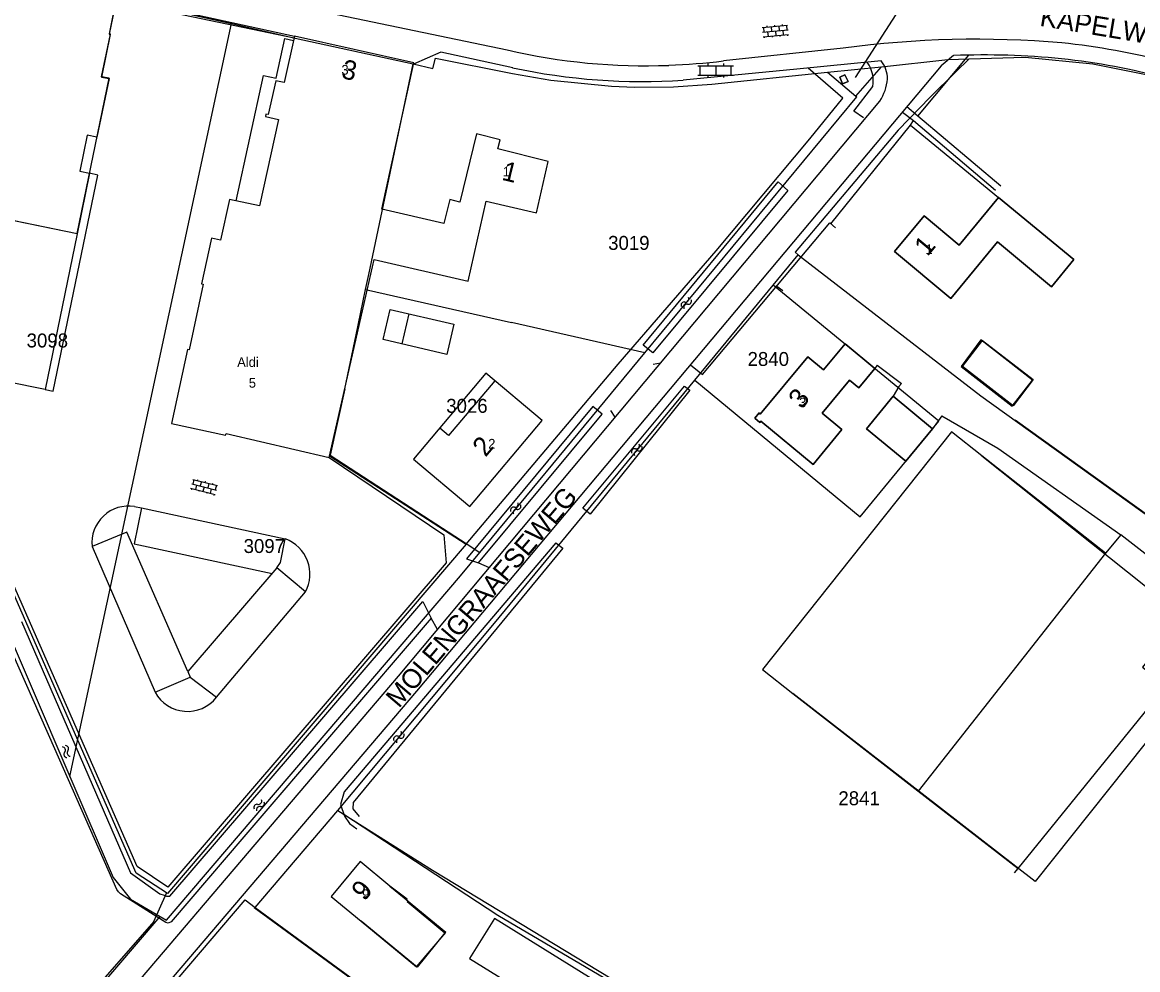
# Model space of a CAD drawing. Extents: x 148816 to 151297, y 399515 to 402500.
# Drawn here: x 149556.2 to 149700.3, y 399853.8 to 399976.1 of the extents above; entities that cross this region are included whole.
import ezdxf

# ---------------------------------------------------------------- set-up
doc = ezdxf.new("R2010")
doc.units = 0
for name, color, linetype in [('B01 Hoofdgebouw  [D] Norm', 7, 'Continuous'), ('B01 Hoofdgebouw  [T] Norm', 7, 'Continuous'), ('B01 hoofgebouw', 7, 'Continuous'), ('B02 Bijgebouw  [D] Norm', 7, 'Continuous'), ('B02 Bijgebouw  [T] Norm', 7, 'Continuous'), ('B03 Overig opstal  [D] Norm', 7, 'Continuous'), ('G01 perceelsgrens', 7, 'Continuous'), ('Q01 Spoorrail  [D] Norm', 7, 'Continuous'), ('S02 Open verharding  Norm', 7, 'Continuous'), ('S05 Water  Norm', 7, 'Continuous'), ('T04 Haag heg  [D] Gem', 7, 'Continuous'), ('T09 Insteek water  [T] Norm', 7, 'Continuous'), ('V00 Kant verharding algemeen  [T] Norm', 7, 'Continuous'), ('V00 Kant verharding algemeen secundair  [T] Gem', 7, 'Continuous'), ('Z01 perceelnummer', 7, 'Continuous'), ('Z02 huisnummer', 7, 'Continuous'), ('Z02 Huisnummer  [Tekst] Norm', 7, 'Continuous'), ('Z06 straatnaam', 7, 'Continuous'), ('Z19 Overige Tekst  [Tekst] Gem', 7, 'Continuous')]:
    doc.layers.add(name, color=color, linetype=linetype)

msp = doc.modelspace()

# ---------------------------------------------------------------- linework, layer by layer
at = {"layer": 'B01 Hoofdgebouw  [D] Norm'}
for p, q in [((149696.14, 399907.52), (149680.2, 399920.1)), ((149698.12, 399909.89), (149696.14, 399907.52)), ((149711.47, 399899.6), (149698.12, 399909.89)), ((149696.14, 399907.52), (149671.95, 399876.8)), ((149684.88, 399866.84), (149711.47, 399899.6)), ((149655.75, 399889.41), (149671.91, 399876.83)), ((149671.91, 399876.83), (149684.88, 399866.84)), ((149605.93, 399862.88), (149603.68, 399864.52)), ((149605.82, 399862.71), (149605.93, 399862.88)), ((149610.91, 399858.57), (149605.82, 399862.71)), ((149599.97, 399860.03), (149607.15, 399854.11)), ((149617.21, 399860.35), (149613.99, 399855.18)), ((149645.48, 399842.9), (149617.21, 399860.35)), ((149607.15, 399854.11), (149610.91, 399858.57)), ((149613.99, 399855.18), (149642.3, 399837.81)), ((149613.99, 399855.18), (149613.99, 399855.18))]:
    msp.add_line(p, q, dxfattribs=at)
at = {"layer": 'B01 Hoofdgebouw  [T] Norm'}
for p, q in [((149662.46, 399969.29), (149661.82, 399968.98)), ((149661.82, 399968.98), (149662.18, 399968.14)), ((149662.9, 399968.43), (149662.46, 399969.29)), ((149662.18, 399968.14), (149662.9, 399968.43)), ((149682.32, 399953.48), (149677.26, 399947.3)), ((149692.06, 399945.46), (149682.32, 399953.48)), ((149672.71, 399951.08), (149668.89, 399946.49)), ((149677.26, 399947.3), (149672.71, 399951.08)), ((149676.16, 399940.44), (149682.22, 399947.72)), ((149682.22, 399947.72), (149689.19, 399941.91)), ((149668.89, 399946.49), (149676.16, 399940.44)), ((149689.19, 399941.91), (149692.06, 399945.46)), ((149662.5, 399934.55), (149659.72, 399931.21)), ((149666.34, 399931.37), (149662.5, 399934.55)), ((149657.69, 399932.89), (149651.55, 399925.5)), ((149659.72, 399931.21), (149657.69, 399932.89)), ((149664.28, 399928.88), (149666.34, 399931.37)), ((149659.57, 399925.62), (149663.09, 399929.87)), ((149663.09, 399929.87), (149664.28, 399928.88)), ((149665.28, 399923.61), (149668.74, 399927.79)), ((149668.74, 399927.79), (149673.81, 399923.58)), ((149651.4, 399925.65), (149650.83, 399924.98)), ((149651.55, 399925.5), (149651.4, 399925.65)), ((149662.11, 399923.51), (149659.57, 399925.62)), ((149650.83, 399924.98), (149651.5, 399924.42)), ((149651.5, 399924.42), (149651.64, 399924.59)), ((149651.64, 399924.59), (149658.38, 399919)), ((149676.28, 399923.22), (149651.83, 399892.53)), ((149658.38, 399919), (149662.11, 399923.51)), ((149670.35, 399919.4), (149665.28, 399923.61)), ((149673.81, 399923.58), (149670.35, 399919.4)), ((149680.2, 399920.1), (149676.28, 399923.22)), ((149651.83, 399892.53), (149655.75, 399889.41)), ((149599.83, 399867.71), (149596.11, 399863.22)), ((149603.68, 399864.52), (149599.83, 399867.71)), ((149596.11, 399863.22), (149599.97, 399860.03))]:
    msp.add_line(p, q, dxfattribs=at)
for points in [[(149539.35, 399953.68), (149545.61, 399983.79), (149565.21, 399979.72), (149565.17, 399979.54), (149568.32, 399978.9), (149567.41, 399974.55), (149567.55, 399974.52), (149566.42, 399969.01), (149567.4, 399968.81), (149565.84, 399961.24), (149564.58, 399961.5), (149563.62, 399956.85), (149564.89, 399956.59), (149563.27, 399948.75), (149539.35, 399953.68)], [(149563.27, 399948.75), (149559.13, 399928.66), (149554.23, 399929.67)]]:
    msp.add_lwpolyline(points, dxfattribs=at)
for points in [[(149606.8, 399970.86), (149591.36, 399974.28), (149590.04, 399968.3), (149588.97, 399968.54), (149587.96, 399964.17), (149587.67, 399964.23), (149587.6, 399963.92), (149589.3, 399963.53), (149586.86, 399952.37), (149582.96, 399953.22), (149581.81, 399947.96), (149580.63, 399948.23), (149579.36, 399942.3), (149579.58, 399942.26), (149577.77, 399933.79), (149577.54, 399933.84), (149575.48, 399924.28), (149582.47, 399922.76), (149582.52, 399922.98), (149595.83, 399919.88), (149601.66, 399945.44), (149613.79, 399942.67), (149616.14, 399952.98), (149622.64, 399951.5), (149624.15, 399958.12), (149617.65, 399959.73), (149617.94, 399960.92), (149614.9, 399961.67), (149612.74, 399952.86), (149611.43, 399953.19), (149610.67, 399950.12), (149602.64, 399951.96)], [(149614.01, 399913.55), (149623.37, 399924.66), (149616.09, 399930.76), (149606.75, 399919.67)]]:
    msp.add_lwpolyline(points, close=True, dxfattribs=at)
at = {"layer": 'B01 hoofgebouw'}
for points in [[(149539.4, 399953.71), (149563.3, 399948.8), (149567.42, 399968.85), (149566.44, 399969.05), (149567.57, 399974.56), (149567.45, 399974.58), (149568.34, 399978.92), (149565.19, 399979.57), (149565.23, 399979.74), (149545.63, 399983.78)], [(149624.15, 399958.12), (149617.65, 399959.73), (149617.94, 399960.92), (149614.9, 399961.67), (149612.74, 399952.86), (149611.43, 399953.19), (149610.67, 399950.12), (149602.64, 399951.96), (149606.75, 399970.66), (149606.8, 399970.86), (149591.36, 399974.28), (149590.04, 399968.3), (149588.97, 399968.54), (149587.96, 399964.17), (149587.67, 399964.23), (149587.6, 399963.92), (149589.3, 399963.53), (149586.86, 399952.37), (149582.96, 399953.22), (149581.81, 399947.96), (149580.63, 399948.23), (149579.36, 399942.3), (149579.58, 399942.26), (149577.77, 399933.79), (149577.54, 399933.84), (149575.48, 399924.28), (149582.47, 399922.76), (149582.52, 399922.98), (149595.83, 399919.88)], [(149662.18, 399968.14), (149661.82, 399968.98), (149662.46, 399969.29), (149662.9, 399968.43), (149662.18, 399968.14)], [(149595.83, 399919.88), (149601.66, 399945.44), (149613.79, 399942.67), (149616.14, 399952.98), (149622.64, 399951.5), (149624.15, 399958.12)], [(149672.71, 399951.08), (149677.26, 399947.3), (149682.32, 399953.48), (149692.06, 399945.46), (149689.19, 399941.91), (149682.22, 399947.72), (149676.16, 399940.44), (149668.89, 399946.49), (149672.71, 399951.08)], [(149611.07, 399933.2), (149602.82, 399935.12), (149603.72, 399939.01), (149611.97, 399937.1), (149611.07, 399933.2)], [(149650.83, 399924.98), (149651.4, 399925.65), (149651.55, 399925.5), (149657.69, 399932.89), (149659.72, 399931.21), (149662.5, 399934.55), (149666.34, 399931.37), (149664.28, 399928.88), (149663.09, 399929.87), (149659.57, 399925.62), (149662.11, 399923.51), (149658.38, 399919), (149651.64, 399924.59), (149651.5, 399924.42), (149650.83, 399924.98)], [(149686.82, 399929.95), (149684.21, 399926.57), (149677.67, 399931.64), (149680.27, 399935), (149686.82, 399929.95)], [(149614.01, 399913.55), (149623.37, 399924.66), (149616.09, 399930.76), (149606.75, 399919.67), (149614.01, 399913.55)], [(149668.74, 399927.79), (149665.28, 399923.61), (149670.35, 399919.4), (149673.81, 399923.58), (149668.74, 399927.79)], [(149680.2, 399920.1), (149676.28, 399923.22), (149651.83, 399892.53), (149655.75, 399889.41)], [(149680.2, 399920.1), (149706.18, 399899.4), (149700.94, 399892.82), (149706.02, 399888.9), (149687.08, 399865.13), (149655.75, 399889.41)], [(149603.68, 399864.52), (149599.83, 399867.71), (149596.11, 399863.22), (149599.97, 399860.03)], [(149603.68, 399864.52), (149606.01, 399862.64), (149605.94, 399862.56), (149610.81, 399858.51)], [(149610.81, 399858.51), (149607.2, 399854.07), (149599.97, 399860.03)]]:
    msp.add_lwpolyline(points, dxfattribs=at)
at = {"layer": 'B02 Bijgebouw  [D] Norm'}
for p, q in [((149680.06, 399935.1), (149677.52, 399931.66)), ((149686.72, 399929.89), (149680.06, 399935.1)), ((149677.52, 399931.66), (149684.11, 399926.51)), ((149684.11, 399926.51), (149686.72, 399929.89)), ((149686.72, 399929.89), (149686.72, 399929.89))]:
    msp.add_line(p, q, dxfattribs=at)
at = {"layer": 'B02 Bijgebouw  [T] Norm'}
msp.add_lwpolyline([(149611.07, 399933.2), (149602.82, 399935.12), (149603.72, 399939.01), (149611.97, 399937.1)], close=True, dxfattribs=at)
at = {"layer": 'B03 Overig opstal  [D] Norm'}
msp.add_line((149606.16, 399938.45), (149605.23, 399934.56), dxfattribs=at)
msp.add_lwpolyline([(149617.24, 399929.8), (149611.28, 399922.72), (149610.13, 399923.69)], dxfattribs=at)
at = {"layer": 'G01 perceelsgrens'}
for points in [[(149567.23, 399979.52), (149583.22, 399975.91)], [(149562.35, 399878.68), (149583.22, 399975.91)], [(149583.22, 399975.91), (149591.46, 399974.05), (149606.68, 399970.71)], [(149606.68, 399970.71), (149609.22, 399970.14), (149609.58, 399971.44), (149619.55, 399969.47), (149624.49, 399968.61), (149632.33, 399967.82), (149635.3, 399967.71), (149640.32, 399967.77), (149645.31, 399968.11), (149660.24, 399969.66)], [(149678.53, 399971.35), (149685.79, 399971.6), (149694.54, 399970.72), (149703.15, 399968.98), (149712.62, 399965.67), (149738.18, 399954.78), (149747.36, 399950.83), (149750.02, 399949.48)], [(149600.55, 399941.59), (149600.95, 399943.53), (149606.68, 399970.71)], [(149678.53, 399971.35), (149676.84, 399969.68), (149673.51, 399966.42), (149669.39, 399962.16), (149656.05, 399946.39), (149656.45, 399946.07)], [(149660.24, 399969.66), (149667.23, 399970.35)], [(149663.89, 399966.54), (149667.23, 399970.35)], [(149667.23, 399970.35), (149675.78, 399971.26), (149678.53, 399971.35)], [(149660.24, 399969.66), (149663.89, 399966.54)], [(149636.65, 399933.4), (149664.01, 399966.44), (149663.89, 399966.54)], [(149653.21, 399942.14), (149656.45, 399946.07)], [(149656.45, 399946.07), (149680.04, 399927.84), (149734.15, 399889.05)], [(149599.33, 399935.71), (149600.55, 399941.59)], [(149600.55, 399941.59), (149619.4, 399937.32)], [(149643.11, 399929.88), (149664.46, 399912.24), (149674.64, 399924.6), (149653.21, 399942.14)], [(149643.11, 399929.88), (149653.21, 399942.14)], [(149636.65, 399933.4), (149619.4, 399937.32)], [(149597.88, 399928.76), (149599.33, 399935.71)], [(149632.33, 399928.18), (149636.65, 399933.4)], [(149596.96, 399874.3), (149617.22, 399898.48), (149643.11, 399929.88)], [(149597.88, 399928.76), (149595.97, 399920.18)], [(149615.31, 399907.63), (149632.33, 399928.18)], [(149595.97, 399920.18), (149608.04, 399912.34)], [(149547.19, 399913.98), (149562.35, 399878.68)], [(149608.04, 399912.34), (149613.67, 399908.69)], [(149613.67, 399908.69), (149615.31, 399907.63)], [(149612.82, 399904.62), (149615.31, 399907.63)], [(149574.02, 399860.62), (149574.81, 399860.15), (149612.82, 399904.62)], [(149562.35, 399878.68), (149567.95, 399865.64), (149570.18, 399862.88), (149574.02, 399860.62)], [(149586.3, 399861.77), (149596.96, 399874.3)], [(149596.96, 399874.3), (149609.21, 399866.6), (149652.26, 399840.54), (149650.89, 399833.39), (149685.52, 399809.42)], [(149552.31, 399731.81), (149538.32, 399785.32), (149537.24, 399793.27), (149538.02, 399800.67), (149540.43, 399807.68), (149544.81, 399814.17), (149544.03, 399814.85), (149584.99, 399862.77), (149586.3, 399861.77)], [(149530.37, 399795.59), (149531.12, 399802.31), (149534.21, 399810.97), (149539.3, 399818.63), (149538.57, 399819.27), (149574.02, 399860.62)], [(149586.3, 399861.77), (149675.13, 399796.74)]]:
    msp.add_lwpolyline(points, dxfattribs=at)
at = {"layer": 'Q01 Spoorrail  [D] Norm'}
for radius in [839.82, 838.32]:
    msp.add_arc((149374.9, 399222.57), radius, 47.97661, 67.90149, dxfattribs=at)
at = {"layer": 'S02 Open verharding  Norm'}
for p, q in [((149651.8, 399975.41), (149655.08, 399975.71)), ((149653.44, 399975.56), (149653.43, 399975.71)), ((149654.44, 399975.65), (149654.42, 399975.8)), ((149651.85, 399974.81), (149655.14, 399975.11)), ((149651.91, 399974.21), (149655.19, 399974.51)), ((149651.95, 399975.42), (149652, 399974.82)), ((149652.45, 399975.47), (149652.43, 399975.62)), ((149652.5, 399974.87), (149652.55, 399974.27)), ((149652.94, 399975.51), (149653, 399974.92)), ((149653.05, 399974.32), (149653.07, 399974.17)), ((149653.5, 399974.96), (149653.55, 399974.36)), ((149653.94, 399975.6), (149653.99, 399975.01)), ((149654.05, 399974.41), (149654.06, 399974.26)), ((149654.55, 399974.45), (149654.49, 399975.05)), ((149654.93, 399975.69), (149654.99, 399975.1)), ((149655.04, 399974.5), (149655.06, 399974.35)), ((149652.06, 399974.23), (149652.07, 399974.08)), ((149643.49, 399970.45), (149648.09, 399970.45)), ((149643.79, 399969.25), (149643.79, 399970.45)), ((149644.79, 399970.75), (149644.79, 399970.45)), ((149645.79, 399970.45), (149645.79, 399969.25)), ((149646.79, 399970.75), (149646.79, 399970.45)), ((149647.79, 399969.25), (149647.79, 399970.45)), ((149643.49, 399969.25), (149648.09, 399969.25)), ((149644.79, 399969.25), (149644.79, 399968.95)), ((149646.79, 399969.25), (149646.79, 399968.95)), ((149578.22, 399917.07), (149581.42, 399916.27)), ((149578.37, 399917.03), (149578.22, 399916.45)), ((149578.85, 399916.91), (149578.89, 399917.06)), ((149579.34, 399916.79), (149579.19, 399916.21)), ((149579.82, 399916.67), (149579.86, 399916.82)), ((149577.93, 399915.91), (149581.13, 399915.11)), ((149578.08, 399915.87), (149578.04, 399915.72)), ((149578.08, 399916.49), (149581.28, 399915.69)), ((149578.71, 399916.33), (149578.56, 399915.75)), ((149579.05, 399915.63), (149579.01, 399915.48)), ((149579.68, 399916.09), (149579.53, 399915.51)), ((149580.02, 399915.39), (149579.98, 399915.24)), ((149580.31, 399916.55), (149580.16, 399915.97)), ((149580.5, 399915.26), (149580.65, 399915.85)), ((149580.79, 399916.43), (149580.83, 399916.57)), ((149581.28, 399916.31), (149581.13, 399915.73)), ((149580.99, 399915.14), (149580.95, 399915))]:
    msp.add_line(p, q, dxfattribs=at)
at = {"layer": 'S05 Water  Norm'}
for centre, start, end in [((149641.73, 399939.55), 78.5608, 202.4158), ((149642.08, 399939.26), 78.5608, 202.4158), ((149641.9, 399940.38), 258.5608, 22.4158), ((149642.25, 399940.1), 258.5608, 22.4158), ((149635.34, 399920.6), 78.5608, 202.4158), ((149635.51, 399921.44), 258.5608, 22.4158), ((149635.85, 399921.15), 258.5608, 22.4158), ((149635.68, 399920.32), 78.5608, 202.4158), ((149619.86, 399913.89), 258.4991, 22.3541), ((149620.21, 399913.61), 258.4991, 22.3541), ((149619.69, 399913.06), 78.4991, 202.3541), ((149620.04, 399912.77), 78.4991, 202.3541), ((149604.6, 399883.51), 78.5608, 202.4158), ((149604.95, 399883.23), 78.5608, 202.4158), ((149604.77, 399884.35), 258.5608, 22.4158), ((149605.11, 399884.06), 258.5608, 22.4158), ((149561.34, 399882.11), 320.4187, 84.2737), ((149561.75, 399882.28), 320.4187, 84.2737), ((149561.99, 399881.56), 140.4187, 264.2737), ((149562.41, 399881.74), 140.4187, 264.2737), ((149586.53, 399874.69), 77.4834, 201.3384), ((149586.87, 399874.4), 77.4834, 201.3384), ((149586.71, 399875.52), 257.4833, 21.3384), ((149587.05, 399875.23), 257.4833, 21.3384)]:
    msp.add_arc(centre, 0.425, start, end, dxfattribs=at)
at = {"layer": 'T04 Haag heg  [D] Gem'}
for p, q in [((149671.89, 399963.98), (149678.5, 399971.85)), ((149662.23, 399966.29), (149657.75, 399970.18)), ((149657.94, 399961.02), (149662.23, 399966.29)), ((149660.69, 399950.05), (149670.95, 399962.79)), ((149670.95, 399962.79), (149671.33, 399963.4)), ((149670.95, 399962.79), (149682.32, 399953.48)), ((149645.85, 399946.57), (149657.94, 399961.02)), ((149633.21, 399931.93), (149645.85, 399946.57)), ((149613.53, 399908.72), (149633.21, 399931.93)), ((149684.49, 399924.75), (149708.36, 399907.61)), ((149597.61, 399873.94), (149617.62, 399860.81)), ((149573.18, 399859.96), (149574.84, 399863.65)), ((149586.15, 399861.77), (149603.65, 399849)), ((149617.62, 399860.81), (149635.77, 399850.14))]:
    msp.add_line(p, q, dxfattribs=at)
for points in [[(149591.31, 399974.04), (149568.31, 399978.83)], [(149595.88, 399920.09), (149613.53, 399908.72), (149574.96, 399863.58), (149570.89, 399866.2), (149549.84, 399914.14), (149546.04, 399915.34), (149539.65, 399953.62)], [(149573.18, 399859.96), (149538.99, 399820.92), (149531.89, 399807.8), (149529.03, 399799.52), (149529.74, 399795.41)]]:
    msp.add_lwpolyline(points, dxfattribs=at)
at = {"layer": 'T09 Insteek water  [T] Norm'}
for p, q in [((149560.38, 399882.28), (149550.53, 399904.52)), ((149591.23, 399881.84), (149607.94, 399901.31)), ((149607.94, 399901.31), (149609.03, 399899.15)), ((149556.1, 399898.7), (149565.21, 399877.68)), ((149609.03, 399899.15), (149584.8, 399870.93)), ((149568.39, 399864.12), (149560.38, 399882.28)), ((149575.25, 399863.24), (149591.23, 399881.84)), ((149565.21, 399877.68), (149570.19, 399866.26)), ((149598.92, 399874.51), (149599.71, 399873.54)), ((149584.8, 399870.93), (149575.43, 399859.93)), ((149570.19, 399866.26), (149573.98, 399863.54)), ((149568.62, 399863.82), (149568.39, 399864.12)), ((149568.87, 399863.56), (149568.62, 399863.82)), ((149574.39, 399860.06), (149568.87, 399863.56)), ((149573.98, 399863.54), (149574.52, 399863.37)), ((149574.52, 399863.37), (149574.82, 399863.24)), ((149574.82, 399863.24), (149575.25, 399863.24)), ((149574.75, 399859.83), (149574.39, 399860.06)), ((149575.05, 399859.78), (149574.75, 399859.83)), ((149575.43, 399859.93), (149575.05, 399859.78))]:
    msp.add_line(p, q, dxfattribs=at)
for points in [[(149653.88, 399955.47), (149655.12, 399954.38), (149637.68, 399933.39), (149636.41, 399934.38)], [(149615.13, 399906.28), (149631.11, 399925.49), (149629.93, 399926.47), (149613.6, 399906.79)]]:
    msp.add_lwpolyline(points, close=True, dxfattribs=at)
for points in [[(149641.77, 399929.1), (149642.47, 399928.59), (149629.55, 399912.58), (149628.62, 399913.34), (149641.77, 399929.1)], [(149625.14, 399908.87), (149597.78, 399876.7), (149597.33, 399875.09)], [(149625.14, 399908.87), (149626.05, 399908.2), (149598.95, 399875.35), (149598.92, 399874.51)], [(149597.33, 399875.09), (149597.82, 399873.57), (149598.46, 399872.65), (149599.41, 399871.96)]]:
    msp.add_lwpolyline(points, dxfattribs=at)
msp.add_arc((149548.23, 399938.46), 200.04, 318.2664, 337.6939, dxfattribs=at)
at = {"layer": 'V00 Kant verharding algemeen  [T] Norm'}
for p, q in [((149542.19, 399985.07), (149591.36, 399974.28)), ((149610.26, 399972.21), (149606.75, 399970.66)), ((149619.56, 399970.22), (149610.26, 399972.21)), ((149662.26, 399972.74), (149646.79, 399971.09)), ((149676.54, 399971.79), (149674.93, 399970.45)), ((149674.93, 399970.45), (149607.15, 399889.73)), ((149656.26, 399970.04), (149641.6, 399968.6)), ((149667.16, 399971.09), (149656.26, 399970.04)), ((149663.66, 399964.61), (149666.09, 399967.79)), ((149604.8, 399891.66), (149666.99, 399965.91)), ((149664.88, 399963.75), (149663.66, 399964.61)), ((149669.94, 399964.5), (149671.33, 399963.4)), ((149671.89, 399963.98), (149670.5, 399965.18)), ((149671.33, 399963.4), (149681.96, 399954.41)), ((149682.64, 399954.94), (149671.89, 399963.98)), ((149666.65, 399931.82), (149666.34, 399931.37)), ((149666.65, 399931.82), (149669.8, 399929.45)), ((149669.45, 399929.04), (149668.74, 399927.79)), ((149669.8, 399929.45), (149669.45, 399929.04)), ((149675.01, 399925.25), (149673.81, 399923.58)), ((149675.01, 399925.25), (149682.26, 399921.11)), ((149682.26, 399921.11), (149698.12, 399909.89)), ((149571.59, 399913.4), (149590.18, 399909.38)), ((149565.22, 399908.4), (149573.37, 399889.58)), ((149615.13, 399906.28), (149616.53, 399905.67)), ((149581.28, 399888.93), (149592.8, 399902.53)), ((149609.84, 399897.67), (149609.03, 399899.15)), ((149561.45, 399840.79), (149604.8, 399891.66)), ((149607.15, 399889.73), (149565.03, 399840.36)), ((149684.42, 399866.28), (149684.88, 399866.84))]:
    msp.add_line(p, q, dxfattribs=at)
for points in [[(149486.38, 400000), (149546.61, 399987.56), (149548.16, 399985.24), (149571.78, 399980.22), (149574.3, 399981.82), (149618.85, 399972.52)], [(149583.83, 399953.03), (149587.36, 399969.21), (149588.98, 399968.85), (149590.13, 399974.01), (149591.24, 399973.74)], [(149559.13, 399928.66), (149560.18, 399928.44), (149565.97, 399956.36), (149564.89, 399956.59)], [(149595.83, 399919.88), (149610.65, 399909.91), (149610.95, 399906.29), (149575, 399864.4), (149571.02, 399867.09), (149550.12, 399914.63), (149546.57, 399915.67), (149540.18, 399953.51)], [(149642.54, 399931.87), (149644.07, 399930.59), (149660.53, 399950.19)], [(149570.69, 399913.57), (149571.59, 399913.4), (149570.66, 399908.74), (149588.48, 399904.92)], [(149577.59, 399892.24), (149569.69, 399910.27), (149565.22, 399908.4)], [(149589.1, 399905.65), (149589.55, 399906.32), (149590.18, 399909.38)], [(149592.8, 399902.53), (149589.1, 399905.65), (149577.59, 399892.24), (149577.9, 399891.52), (149581.28, 399888.93)], [(149573.37, 399889.58), (149577.88, 399891.52)]]:
    msp.add_lwpolyline(points, dxfattribs=at)
for centre, radius, start, end in [((149679.51, 399845.13), 128.77, 85.0997, 97.6986), ((149681.22, 399883.47), 90.44, 66.3139, 84.1031), ((149636.72, 400049.56), 79.09, 256.9347, 272.181), ((149680.5, 399873.96), 97.91, 84.1489, 92.3174), ((149636.36, 400048.22), 79.79, 257.8407, 273.7618), ((149636.09, 400060.84), 90.38, 272.3088, 276.7978), ((149662.11, 399968.52), 4.05, 349.6841, 36.2888), ((149664.62, 399968.89), 3.36, 357.6708, 40.9529), ((149681.21, 399883.78), 88.07, 65.9442, 83.9574), ((149662.08, 399969.22), 5.92, 326.0685, 355.4953), ((149569.93, 399908.88), 4.74, 80.7123, 185.8775), ((149588.47, 399904.8), 4.89, 332.3359, 69.4968), ((149577.53, 399891.84), 4.74, 208.5517, 322.1478)]:
    msp.add_arc(centre, radius, start, end, dxfattribs=at)
at = {"layer": 'V00 Kant verharding algemeen secundair  [T] Gem'}
for p, q in [((149660.53, 399950.19), (149661.29, 399949.54)), ((149653.67, 399942.02), (149654.48, 399941.44))]:
    msp.add_line(p, q, dxfattribs=at)
for points in [[(149637.69, 399931.93), (149638.68, 399932.11)], [(149632.81, 399925.1), (149632.25, 399925.94)]]:
    msp.add_lwpolyline(points, dxfattribs=at)
at = {"layer": 'Z01 perceelnummer'}
msp.add_lwpolyline([(149669.44, 399977.69), (149663.83, 399968.96)], dxfattribs=at)

# ---------------------------------------------------------------- texts
for s, p in [('3019', (149631.89, 399946.7)), ('3098', (149556.75, 399934.1)), ('2840', (149649.91, 399931.71)), ('3026', (149610.97, 399925.66)), ('3097', (149584.79, 399907.56)), ('2841', (149661.64, 399874.99))]:
    msp.add_text(s, height=1.8, dxfattribs=at).set_placement(p)
at = {"layer": 'Z02 huisnummer'}
for s, rotation, p in [('3', 347.5892, (149597.3, 399968.9)), ('1', 346.1722, (149618.04, 399955.77)), ('1', 50.2751, (149673.16, 399945.76)), ('3', 50.2751, (149656.89, 399926.06)), ('2', 49.8645, (149616.05, 399919.85)), ('9', 50.3558, (149600.43, 399862.56))]:
    msp.add_text(s, height=2.5, rotation=rotation, dxfattribs=at).set_placement(p)
at = {"layer": 'Z02 Huisnummer  [Tekst] Norm'}
for s, p in [('3', (149597.43, 399969.33)), ('1', (149618.27, 399956.18)), ('1', (149672.9, 399946.15)), ('5', (149585.46, 399928.9)), ('3', (149656.56, 399926.37)), ('2', (149616.4, 399921.04)), ('9', (149600.1, 399862.87))]:
    msp.add_text(s, height=1.25, dxfattribs=at).set_placement(p)
at = {"layer": 'Z06 straatnaam'}
for s, rotation, p in [('KAPELWEG', 350.5, (149687.57, 399975.64)), ('MOLENGRAAFSEWEG', 49.666, (149604.86, 399887.43))]:
    msp.add_text(s, height=2.5, rotation=rotation, dxfattribs=at).set_placement(p)
at = {"layer": 'Z19 Overige Tekst  [Tekst] Gem'}
msp.add_text('Aldi', height=1.25, dxfattribs=at).set_placement((149583.96, 399931.58))

doc.saveas('drawing.dxf')
